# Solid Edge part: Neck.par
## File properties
Title: Neck
Author: DESYS
Template: Normal.par
Last saved by: Luca
Revision: 7
Application: Solid Edge
Tipo di contenuto documento: 0
Precisione: 0,990
Document Number: 8045
Revision: 0
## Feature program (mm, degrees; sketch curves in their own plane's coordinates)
lofted protrusion "unnamed LoftedProtrusion 1"
sketch for "unnamed Protrusion 1" plane through (0, 0, -128) normal (0, 0, -1) x-axis (1, 0, 0)
extrude "unnamed Protrusion 1" add finite 20 along +normal
lofted cutout "unnamed LoftedCutout 1"
sketch for "Foro_1" plane through (0, 0, -148) normal (0, 0, -1) x-axis (-1, 0, 0)
  hole centre (0, 0) bore radius 25
hole "Foro_1" diameter 50 through
sketch for "Foro_2" plane through (0, 0, -148) normal (0, 0, -1) x-axis (-1, 0, 0)
  hole centre (160, 0) bore radius 6
hole "Foro_2" diameter 12 finite
sketch for "unnamed Hole 1" plane through (0, 0, -148) normal (0, 0, -1) x-axis (-1, 0, 0)
  hole centre (-160, 0) bore radius 6
hole "unnamed Hole 1" finite
sketch for "Foro_4" plane through (0, 0, -148) normal (0, 0, -1) x-axis (-1, 0, 0)
  hole centre (-160, 0) bore radius 8
hole "Foro_4" diameter 16 finite
sketch for "unnamed Hole 2" plane through (0, 0, -148) normal (0, 0, -1) x-axis (-1, 0, 0)
  hole centre (160, 0) bore radius 8
hole "unnamed Hole 2" finite
sketch for "ExtrudedCutout_1" #1 plane through (0, 0, -148) normal (0, 0, -1) x-axis (-1, 0, 0)
  circle centre (0, 0) radius 39
sketch for "ExtrudedCutout_1" #2 plane through (0, 0, -148) normal (0, 0, -1) x-axis (-1, 0, 0)
  line (-120.4775, 7.7748) -> (-132.6618, 15.8764)
  arc centre (-136.5377, 10.0473) radius 7 from (-132.6618, 15.8764) to (-143.257, 12.0095) ccw
  arc centre (112.4364, -40.5543) radius 7 from (116.3761, -34.7682) to (116.5405, -46.225) cw
  line (106.5212, -28.058) -> (116.3761, -34.7682)
  arc centre (113.5564, -17.7258) radius 12.5 from (106.5212, -28.058) to (120.4775, -7.3167) cw
  line (120.4775, -7.3167) -> (132.7654, -15.4871)
  arc centre (136.6412, -9.6581) radius 7 from (132.7654, -15.4871) to (143.3781, -11.5592) ccw
  arc centre (-112.0286, 40.7348) radius 7 from (-115.9684, 34.9487) to (-116.0976, 46.4308) cw
  line (-106.5212, 28.5162) -> (-115.9684, 34.9487)
extrude "ExtrudedCutout_1" cut finite 10 along -normal  Treatment1_DraftAngle = 25 deg
sketch for "Foro_6" plane through (0, 0, -148) normal (0, 0, -1) x-axis (-1, 0, 0)
  hole centre (-125, 25) bore radius 6
  dimension = 25
  dimension (linear) = 25
  dimension (linear) = 25
hole "Foro_6" diameter 12 finite
sketch for "Foro_7" plane through (0, 0, -148) normal (0, 0, -1) x-axis (1, 0, 0)
  hole centre (-125, 25) bore radius 8
  dimension = 25
  dimension (linear) = 125
  dimension (linear) = 125
hole "Foro_7" diameter 16 finite
fillet "Rotondo_1" radius 5
fillet "Rotondo_2" radius 10
fillet "Rotondo_3" radius 3
fillet "Rotondo_4" radius 7
fillet "Rotondo_5" radius 6
fillet "Rotondo_6" radius 10
pattern "unnamed Pattern 1" of "Foro_2", "unnamed Hole 1"
pattern "unnamed Pattern 2" of "Foro_4", "unnamed Hole 2"
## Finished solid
Body 1: solid body, 64 faces, 111 edges, 48 vertices.
  Faces by surface: cylinder 15, plane 14, torus 14, blend 9, cone 7, spline 4, swept 1
  Edges by curve: circle 57, line 24, intersection 18, curve on surface 12
Bounding box of the edges (mm; curved faces can reach further): 632.460 x 452.334 x 148.000, from (-316.2298, -226.1671, -148) to (316.2298, 226.1671, 0).
Cylindrical faces by radius (mm): R3 x4, R5 x4, R6 x3, R8 x3, R25 x1
Conical faces (half-angle, radius in mm at the cone's reference point): 25 deg R7 x4, 25 deg R12.5 x2, 25 deg R39 x1
Toroidal faces (ring radius, tube radius in mm): R0.4257 r3 x4, R9.3146 r5 x2, R10.1854 r5 x4, R19.0743 r3 x2, R35.8146 r5 x1, R48.1226 r7 x1
Planar faces by outward normal: +z 1, -z 9, oblique 4
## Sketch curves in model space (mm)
arc centre (0, -90.4613, 250.7937) radius 396 from (0, 216, 0) through (0, 129.9943, -78.1673) to (0, 25, -128)
arc centre (0, 90.4613, 250.7937) radius 396 from (0, -216, 0) through (0, -129.9943, -78.1673) to (0, -25, -128)
arc centre (14.3341, 0, 267.8563) radius 396 from (306, 0, 0) through (178.4899, 0, -92.5169) to (25, 0, -128)
arc centre (-14.3341, 0, 267.8563) radius 396 from (-306, 0, 0) through (-178.4899, 0, -92.5169) to (-25, 0, -128)
circle centre (0, 0, -128) radius 25
ellipse centre (0, 0, 0) radii 306, 216
arc centre (0, 18.199, 89.668) radius 230 from (0, 230, 0) through (0, 174.914, -78.6781) to (0, 92.5, -128)
arc centre (0, -18.199, 89.668) radius 230 from (0, -230, 0) through (0, -174.914, -78.6781) to (0, -92.5, -128)
arc centre (107.7692, 0, 88.6458) radius 230 from (320, 0, 0) through (266.019, 0, -78.2583) to (185, 0, -128)
arc centre (-107.7692, 0, 88.6458) radius 230 from (-320, 0, 0) through (-266.019, 0, -78.2583) to (-185, 0, -128)
ellipse centre (0, 0, -128) radii 185, 92.5
ellipse centre (0, 0, 0) radii 320, 230
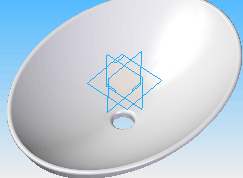
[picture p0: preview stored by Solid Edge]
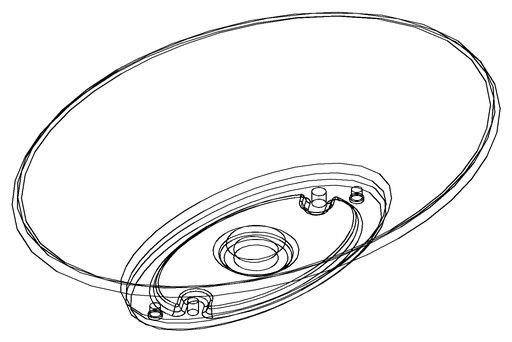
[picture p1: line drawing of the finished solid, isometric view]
